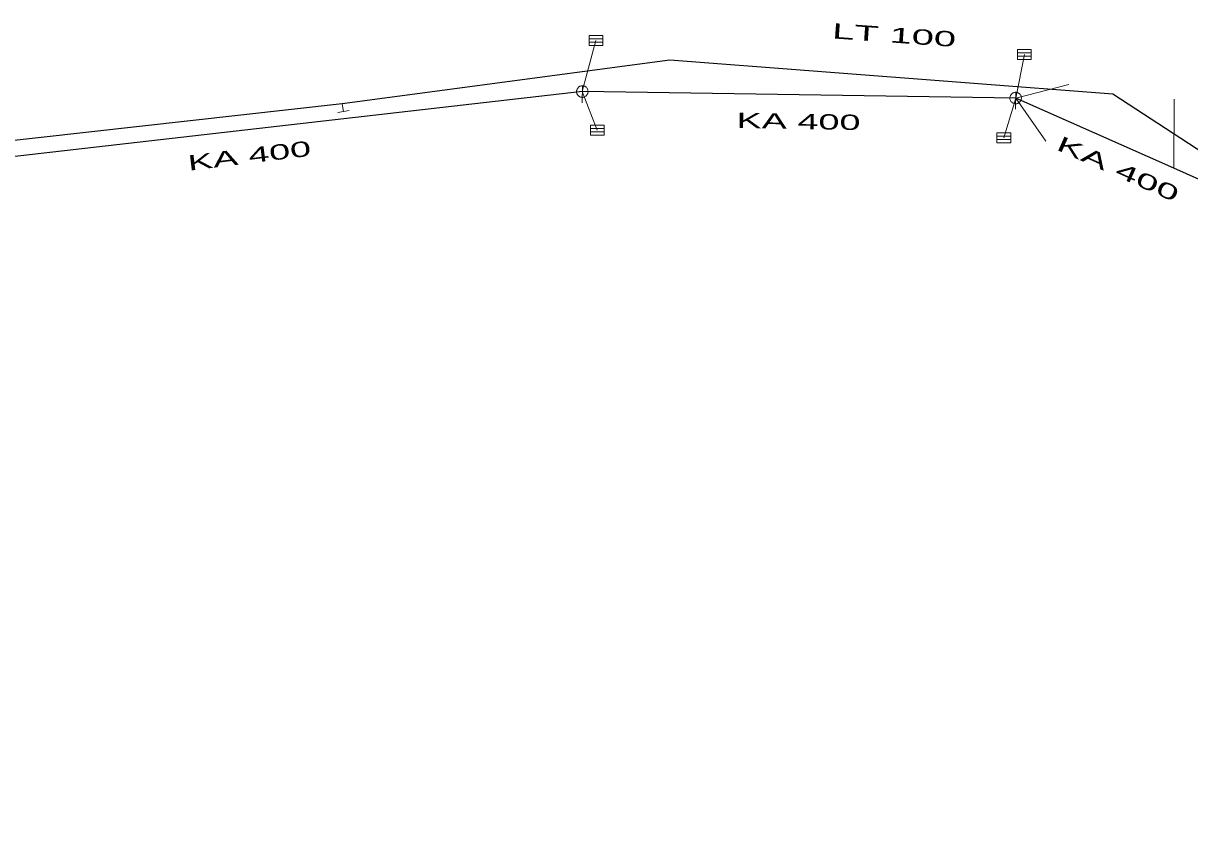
# Model space of a CAD drawing. Extents: x -687468 to -685917, y -974192 to -973456.
# Drawn here: x -686486.5 to -686435.6, y -973750.3 to -973715.2 of the extents above; entities that cross this region are included whole.
import ezdxf
from ezdxf.enums import TextEntityAlignment as Align

# ---------------------------------------------------------------- set-up
doc = ezdxf.new("R2010")
doc.units = 0
doc.header["$LTSCALE"] = 0.27
for name, color, linetype, lineweight in [('1', 7, 'Continuous', 13), ('11', 7, 'Continuous', 13), ('14', 7, 'Continuous', 25), ('17', 7, 'Continuous', 25), ('22', 7, 'Continuous', 13), ('34', 7, 'Continuous', 13)]:
    doc.layers.add(name, color=color, linetype=linetype, lineweight=lineweight)

msp = doc.modelspace()

# ---------------------------------------------------------------- linework, layer by layer
at = {"layer": '11'}
for p, q in [((-686461.54, -973715.97), (-686462.13, -973718.2)), ((-686442.84, -973716.579), (-686443.219, -973718.48)), ((-686461.48, -973719.88), (-686462.13, -973718.2)), ((-686440.897, -973717.888), (-686443.219, -973718.48)), ((-686443.739, -973720.21), (-686443.219, -973718.48)), ((-686441.898, -973720.36), (-686443.219, -973718.48)), ((-686436.306, -973718.535), (-686436.316, -973721.542))]:
    msp.add_line(p, q, dxfattribs=at)
at = {"layer": '14'}
for p, q in [((-686462.129, -973718.199), (-686491.399, -973721.55)), ((-686443.219, -973718.48), (-686462.129, -973718.199))]:
    msp.add_line(p, q, dxfattribs=at)
at = {"layer": '14', "lineweight": 13}
msp.add_line((-686472.603, -973718.727), (-686472.549, -973719.069), dxfattribs=at)
at = {"layer": '14'}
msp.add_lwpolyline([(-686433.55, -973722.77), (-686436.316, -973721.542), (-686443.219, -973718.48)], dxfattribs=at)
at = {"layer": '17'}
msp.add_lwpolyline([(-686390.795, -973750.272), (-686404.794, -973749.853), (-686409.23, -973746.732), (-686417.835, -973738.241), (-686428.076, -973725.42), (-686438.98, -973718.313), (-686458.311, -973716.826), (-686472.603, -973718.727), (-686490.318, -973720.708), (-686506.346, -973717.746)], dxfattribs=at)
at = {"layer": '22'}
for p, q in [((-686461.835, -973715.899), (-686461.237, -973715.899)), ((-686461.835, -973716.044), (-686461.237, -973716.044)), ((-686443.135, -973716.509), (-686442.537, -973716.509)), ((-686443.135, -973716.654), (-686442.537, -973716.654)), ((-686462.129, -973717.948), (-686462.13, -973718.691)), ((-686443.219, -973718.228), (-686443.22, -973718.972)), ((-686461.775, -973719.809), (-686461.177, -973719.809)), ((-686461.775, -973719.955), (-686461.177, -973719.955)), ((-686444.035, -973720.139), (-686443.437, -973720.139)), ((-686444.035, -973720.284), (-686443.437, -973720.284))]:
    msp.add_line(p, q, dxfattribs=at)
for points in [[(-686461.835, -973715.753), (-686461.237, -973715.753), (-686461.237, -973716.19), (-686461.835, -973716.19)], [(-686443.135, -973716.363), (-686442.537, -973716.363), (-686442.537, -973716.799), (-686443.135, -973716.799)], [(-686461.878, -973718.2), (-686461.879, -973718.174), (-686461.883, -973718.148), (-686461.889, -973718.122), (-686461.899, -973718.098), (-686461.911, -973718.074), (-686461.925, -973718.052), (-686461.942, -973718.031), (-686461.96, -973718.013), (-686461.981, -973717.996), (-686462.003, -973717.982), (-686462.027, -973717.97), (-686462.051, -973717.96), (-686462.077, -973717.954), (-686462.103, -973717.95), (-686462.129, -973717.948), (-686462.155, -973717.949), (-686462.181, -973717.953), (-686462.207, -973717.959), (-686462.232, -973717.969), (-686462.255, -973717.981), (-686462.277, -973717.995), (-686462.298, -973718.012), (-686462.316, -973718.03), (-686462.333, -973718.051), (-686462.347, -973718.073), (-686462.359, -973718.097), (-686462.369, -973718.121), (-686462.376, -973718.147), (-686462.38, -973718.173), (-686462.382, -973718.199), (-686462.381, -973718.225), (-686462.377, -973718.251), (-686462.37, -973718.277), (-686462.36, -973718.302), (-686462.348, -973718.325), (-686462.334, -973718.347), (-686462.317, -973718.368), (-686462.299, -973718.386), (-686462.278, -973718.403), (-686462.256, -973718.417), (-686462.233, -973718.429), (-686462.208, -973718.439), (-686462.182, -973718.446), (-686462.156, -973718.45), (-686462.13, -973718.451), (-686462.104, -973718.451), (-686462.078, -973718.447), (-686462.052, -973718.44), (-686462.028, -973718.43), (-686462.004, -973718.418), (-686461.982, -973718.404), (-686461.961, -973718.387), (-686461.943, -973718.369), (-686461.926, -973718.348), (-686461.912, -973718.326), (-686461.9, -973718.303), (-686461.89, -973718.278), (-686461.884, -973718.252), (-686461.88, -973718.226)], [(-686442.968, -973718.48), (-686442.969, -973718.454), (-686442.973, -973718.428), (-686442.979, -973718.402), (-686442.989, -973718.378), (-686443.001, -973718.354), (-686443.015, -973718.332), (-686443.032, -973718.311), (-686443.05, -973718.293), (-686443.071, -973718.276), (-686443.093, -973718.262), (-686443.117, -973718.25), (-686443.141, -973718.24), (-686443.167, -973718.234), (-686443.193, -973718.23), (-686443.219, -973718.228), (-686443.245, -973718.229), (-686443.271, -973718.233), (-686443.297, -973718.239), (-686443.322, -973718.249), (-686443.345, -973718.261), (-686443.367, -973718.275), (-686443.388, -973718.292), (-686443.406, -973718.31), (-686443.423, -973718.331), (-686443.437, -973718.353), (-686443.449, -973718.377), (-686443.459, -973718.401), (-686443.466, -973718.427), (-686443.47, -973718.453), (-686443.472, -973718.479), (-686443.471, -973718.505), (-686443.467, -973718.531), (-686443.46, -973718.557), (-686443.45, -973718.582), (-686443.438, -973718.605), (-686443.424, -973718.627), (-686443.407, -973718.648), (-686443.389, -973718.666), (-686443.368, -973718.683), (-686443.346, -973718.697), (-686443.323, -973718.709), (-686443.298, -973718.719), (-686443.272, -973718.726), (-686443.246, -973718.73), (-686443.22, -973718.732), (-686443.194, -973718.731), (-686443.168, -973718.727), (-686443.142, -973718.72), (-686443.118, -973718.71), (-686443.094, -973718.698), (-686443.072, -973718.684), (-686443.051, -973718.667), (-686443.033, -973718.649), (-686443.016, -973718.628), (-686443.002, -973718.606), (-686442.99, -973718.583), (-686442.98, -973718.558), (-686442.974, -973718.532), (-686442.97, -973718.506)], [(-686461.775, -973719.663), (-686461.177, -973719.663), (-686461.177, -973720.1), (-686461.775, -973720.1)], [(-686444.035, -973719.993), (-686443.437, -973719.993), (-686443.437, -973720.429), (-686444.035, -973720.429)]]:
    msp.add_lwpolyline(points, close=True, dxfattribs=at)
at = {"layer": '34'}
msp.add_line((-686472.794, -973719.106), (-686472.303, -973719.031), dxfattribs=at)

# ---------------------------------------------------------------- texts
at = {"layer": '1'}
for s, rotation, width, p in [('LT 100', 356, 1.95, (-686448.546, -973716.065)), ('KA 400', 359, 1.85, (-686452.701, -973719.833)), ('KA 400', 336, 1.95, (-686438.887, -973721.875)), ('KA 400', 7, 1.85, (-686476.619, -973721.325))]:
    msp.add_text(s, height=0.6667, rotation=rotation, dxfattribs=dict(at, width=width)).set_placement(p, align=Align.CENTER)

doc.saveas('drawing.dxf')
